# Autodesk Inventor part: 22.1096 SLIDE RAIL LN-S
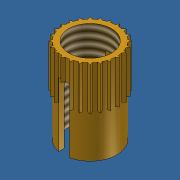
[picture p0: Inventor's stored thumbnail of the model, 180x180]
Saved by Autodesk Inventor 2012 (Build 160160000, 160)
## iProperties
Created: 2007-06
Part Number: 22.1096 SLIDE RAIL LN-S
Material: Brass, Soft Yellow
Document SubType Name: Modeling
Designer: Andy Moles
Density: 8.47 g/cm^3
Mass: 0.455206 g
Surface Area: 2.56671 cm^2
Volume: 0.0537433 cm^3
Author: Andy Moles
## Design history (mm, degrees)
sketch "Sketch1"
  geometry: C1 r 2.5 at (0, 0); C2 r 2 at (0, 0); 1 further point
  constraints: 2 centre point, 2 coincident
  dimensions: "d0" = 5 diameter of C1; "d7" = 4 diameter of C2
extrude "Extrusion1" new body sketch "Sketch1" distance "d1" = 8; taper "d2" = 0 deg
sketch "Sketch2"
  geometry: L1 (-0.144, 2.496)-(0, 2.746); L2 (0, 2.746)-(0.144, 2.496); A1 r 2.5 centre (0, 0) between (-0.144, 2.496) and (0.144, 2.496) reference
  constraints: 4 end point, 2 point on circle, 1 equal length, 1 vertical alignment
  dimensions: "d3" = 0.25 vertical distance of L1.start L1.end; "d4" = 60 deg angle of L2 L1
extrude "Extrusion2" join sketch "Sketch2" distance "d5" = 4; taper "d6" = 0 deg
sketch "Sketch3"
  geometry: L1 (-0.5, 3)-(-0.5, -3); L2 (0.5, -3)-(0.5, 3); L3 (-0.5, 3)-(0.5, 3); L4 (-0.5, -3)-(0.5, -3); C1 r 2 at (0, 0) reference
  constraints: 8 end point, 2 parallel, 1 perpendicular, 1 vertical
  dimensions: "d11" = 0.5 distance from line of C1.centre L1 (= d12); "d12" = 0.5 distance from line of L2 C1.centre; "d13" = 3 distance from line of C1.centre L3; "d14" = 3 distance from line of L4 C1.centre
extrude "Extrusion3" cut sketch "Sketch3" distance "d15" = 6; taper "d16" = 0 deg
thread "Thread1" dims "d17" = 10, "d18" = 0
body "Solid1"
pattern_circular "Circular Pattern1" dims angle "d9" = 360 deg
